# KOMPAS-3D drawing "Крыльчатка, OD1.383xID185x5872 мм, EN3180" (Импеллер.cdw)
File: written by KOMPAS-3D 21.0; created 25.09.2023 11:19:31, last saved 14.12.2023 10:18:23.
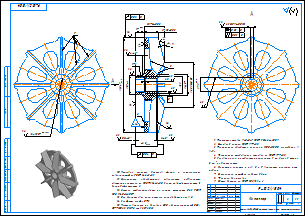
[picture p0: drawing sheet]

Sheet 1: A2, landscape

Document properties: Полное имя файла: D:\Точная технодинамика\04.12.2023\для отправки\центробежный насос P-102 (готово)\P-102A_В.04 - Импеллер.cdw; Автор: Constr2; Знак неуказанной шероховатости: 6

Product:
- Part/product: Крыльчатка, OD1.383xID185x5872 мм  | designation EN3180
    Материал: Сталь 07Х18Н10Г2С2М2Л ГОСТ 977-88 (density 7850 kg/m3)
    Масса: 1238.171927

Title block, sheet 1: Наименование: Импеллер; designation: P-102A/В.04; Материал: Сталь 12Х18Н12М3ТЛ ГОСТ 977-88; Масса: 2; Количество листов документа: 1; organisation: ООО "Точная технодинамика"; Форматы листов документа: A2; stored path: D:\Максимов\Шаблон чертежа.cdt; Разработал: Дущенко; Т. контр.: Серков; Н. контр.: Юсупов; Утвердил: Елагин

Views: Вид по стрелке 1
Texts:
  JS9( 0,018)
  JS9
  импеллер 102.jpg
Dimensions and other numbers on the sheet: 39; 184,7; 6,35; 32; 24,15; 0,5; 1; 17,3; 2,8; 27,2; 41,3; 17; 27,85±0,05; 38,75±0,05; 88,25±0,05; 4; 42,5; 1,6; 6,3; 3,2; 0,03; 0,04; 14; 0,08; 2; 1:1

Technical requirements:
  Точность отливки 9-0-0-9 ГОСТ Р53464-2009.
  Отливка 3 группы ГОСТ 977-88.
  Термическая обработка: закалка с 1100-1150°С, охлаждение в
  воде.
  Технические требования к отливке по ГОСТ 977-88.
  Раковины поры с наибольшим измерением 1 мм более 1 шт на
  5 см 2  не допускается.
  Геометрию лопаток и пов.  В  и  Г  выполнить согласно мат.
  модели.
  Неуказанные литейные радиусы R2 мм.
  *Размеры для справок.
  Общие допуски по ГОСТ 30893.1 - f.
  Числовые значения допусков формы и расположения
  поверхностей по ГОСТ 24643-81.
  Механически обработанные поверхности подвергнуть
  цветному контролю по ГОСТ 18442-80. Класс чувствительности II.
  Класс дефектности 2.
  Деталь отбалансировать по классу точности G6,3 ГОСТ
  ИСО 1940-1-2007.
  При балансировке съем металла производить на пов.  Д .
  Клеймить клеймо ОТК.
  Чертеж выполнен по договору ООО «Красноленинский НПЗ»
  №7710023/0167Д от 12.09.2023.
